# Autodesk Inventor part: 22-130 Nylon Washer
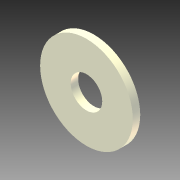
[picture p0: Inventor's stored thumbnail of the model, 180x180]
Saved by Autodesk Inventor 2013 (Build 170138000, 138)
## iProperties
Created: 2004-11
Part Number: 22-130 Nylon Washer
Material: Nylon - 6/6
Document SubType Name: Modeling
Designer: Autodesk, Inc.
Manufacturer: Standard
Standards Organization: Custom
Description: BIN MOUNTING SLIDE RAIL WASHER
Catalog Web Link: http://www.parker.com/ead/cm1.asp?cmid=809
Vendor: PARKER IPS
Mass: 0.981131 g
Surface Area: 10.7874 cm^2
Volume: 0.868258 cm^3
Density: 1.13 g/cm^3
CAGE: 1LJX3
Dept. ID: Product Design
Description #2: ---
Finish #1: ---
Finish #2: ---
Material ID: ---
Project Number: ---
Author: Autodesk, Inc.
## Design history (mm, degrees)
sketch "Sketch1"
  geometry: C1 r 12.5 at (0, 0); C2 r 4.25 at (0, 0)
  constraints: 2 centre point, 1 coincident, 2 other
  dimensions: "d0" = 25 diameter of C1; "d1" = 8.5 diameter of C2
extrude "Extrusion1" new body sketch "Sketch1" distance "d2" = 2; taper "d3" = 0 deg
body "Solid1"
